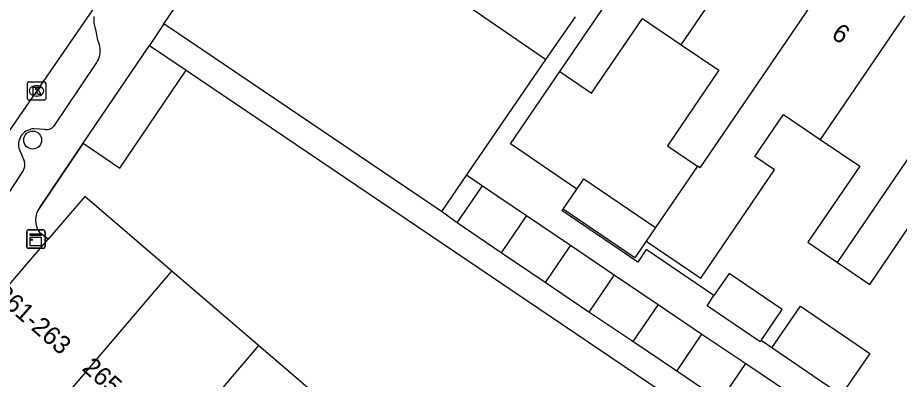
# Model space of a CAD drawing. Extents: x 159280 to 160375, y 384531 to 385872.
# Drawn here: x 159813.38 to 159861.5, y 384790.93 to 384810.68 of the extents above; entities that cross this region are included whole.
import ezdxf

# ---------------------------------------------------------------- set-up
doc = ezdxf.new("R2010")
doc.units = 0
for name, color, linetype in [('IMGEO_Boom', 7, 'Continuous'), ('IMGEO_Kast', 7, 'Continuous'), ('IMGEO_Kolk', 7, 'Continuous'), ('IMGEO_Muur', 7, 'Continuous'), ('IMGEO_Pand', 7, 'Continuous'), ('IMGEO_Pand_nummerreeks', 7, 'Continuous'), ('IMGEO_Rijbaan_lokaal_open', 7, 'Continuous'), ('IMGEO_Voetpad_open', 7, 'Continuous')]:
    doc.layers.add(name, color=color, linetype=linetype)

msp = doc.modelspace()

# ---------------------------------------------------------------- linework, layer by layer
at = {"layer": 'IMGEO_Boom'}
msp.add_circle((159814.205, 384803.995), 0.489, dxfattribs=at)
at = {"layer": 'IMGEO_Kast'}
for p, q in [((159813.878, 384798.159), (159813.878, 384799)), ((159813.878, 384799), (159813.878, 384798.159)), ((159813.953, 384799.084), (159814.794, 384799.084)), ((159814.794, 384799.084), (159813.953, 384799.084)), ((159814.878, 384799.009), (159814.878, 384798.168)), ((159814.878, 384798.168), (159814.878, 384799.009)), ((159814.803, 384798.084), (159813.962, 384798.084)), ((159813.962, 384798.084), (159814.803, 384798.084))]:
    msp.add_line(p, q, dxfattribs=at)
for points in [[(159814.073, 384798.874), (159814.673, 384798.874), (159814.673, 384798.789), (159814.073, 384798.789), (159814.073, 384798.874)], [(159814.073, 384798.699), (159814.673, 384798.699), (159814.673, 384798.21), (159814.073, 384798.21), (159814.073, 384798.699)]]:
    msp.add_lwpolyline(points, dxfattribs=at)
msp.add_circle((159814.157, 384798.548), 0.0377, dxfattribs=at)
for centre, start, end in [((159814.8, 384799.006), 2.4484, 94.2845), ((159814.8, 384799.006), 2.4484, 94.2845), ((159813.956, 384799.006), 92.4484, 184.2845), ((159813.956, 384799.006), 92.4484, 184.2845), ((159813.956, 384798.162), 182.4484, 274.2845), ((159813.956, 384798.162), 182.4484, 274.2845), ((159814.8, 384798.162), 272.4484, 4.2845), ((159814.8, 384798.162), 272.4484, 4.2845)]:
    msp.add_arc(centre, 0.0779, start, end, dxfattribs=at)
at = {"layer": 'IMGEO_Kolk'}
for p, q in [((159813.914, 384806.255), (159813.914, 384807.107)), ((159813.989, 384807.181), (159814.841, 384807.181)), ((159814.402, 384806.961), (159814.427, 384806.961)), ((159814.915, 384807.107), (159814.915, 384806.255)), ((159814.425, 384806.401), (159814.4, 384806.401)), ((159814.841, 384806.181), (159813.989, 384806.181))]:
    msp.add_line(p, q, dxfattribs=at)
for points in [[(159813.914, 384806.255), (159813.914, 384807.107)], [(159813.989, 384807.181), (159814.841, 384807.181)], [(159814.235, 384806.881), (159814.358, 384806.881), (159814.358, 384806.73), (159814.488, 384806.881), (159814.652, 384806.881), (159814.506, 384806.73), (159814.659, 384806.481), (159814.507, 384806.481), (159814.422, 384806.645), (159814.358, 384806.578), (159814.358, 384806.481), (159814.235, 384806.481), (159814.235, 384806.881)], [(159814.915, 384807.107), (159814.915, 384806.255)], [(159814.841, 384806.181), (159813.989, 384806.181)]]:
    msp.add_lwpolyline(points, dxfattribs=at)
for centre, start, end in [((159813.991, 384807.105), 91.552, 178.448), ((159813.991, 384807.105), 91.552, 178.448), ((159814.839, 384807.105), 1.552, 88.448), ((159814.839, 384807.105), 1.552, 88.448), ((159813.991, 384806.257), 181.552, 268.448), ((159813.991, 384806.257), 181.552, 268.448), ((159814.839, 384806.257), 271.552, 358.448), ((159814.839, 384806.257), 271.552, 358.448)]:
    msp.add_arc(centre, 0.0765, start, end, dxfattribs=at)
for centre, major_axis, ratio, start_param, end_param in [((159814.401, 384806.681), (-0.387, 0.002), 0.722429, 4.712389, 7.853982), ((159814.426, 384806.681), (-0.39, 0.002), 0.717154, 1.570796, 4.712389)]:
    msp.add_ellipse(centre, major_axis=major_axis, ratio=ratio, start_param=start_param, end_param=end_param, dxfattribs=at)
at = {"layer": 'IMGEO_Muur'}
for points in [[(159816.958, 384803.823), (159814.598, 384800.315)], [(159815.059, 384798.586), (159814.594, 384798.937)]]:
    msp.add_lwpolyline(points, dxfattribs=at)
msp.add_arc((159815.493, 384799.623), 1.131, 142.3162, 217.3511, dxfattribs=at)
at = {"layer": 'IMGEO_Pand'}
for points in [[(159821.369, 384810.341), (159827.097, 384818.804)], [(159842.964, 384807.74), (159847.547, 384814.471), (159850.361, 384818.603)], [(159849.598, 384809.194), (159854.217, 384815.978)], [(159857.686, 384812.866), (159850.613, 384802.479), (159850.476, 384802.572)], [(159842.197, 384808.391), (159837.892, 384811.347), (159837.962, 384811.45)], [(159843.804, 384810.731), (159842.197, 384808.391)], [(159842.964, 384807.74), (159844.706, 384806.554), (159847.484, 384810.634), (159849.598, 384809.194)], [(159861.787, 384810.787), (159857.182, 384804.026)], [(159836.505, 384800.099), (159825.511, 384807.539), (159821.369, 384810.341)], [(159849.598, 384809.194), (159851.639, 384807.804), (159848.837, 384803.688), (159850.476, 384802.572)], [(159816.958, 384803.823), (159820.573, 384809.165)], [(159820.573, 384809.165), (159822.578, 384807.809)], [(159842.197, 384808.391), (159837.88, 384802.102)], [(159816.958, 384803.823), (159818.963, 384802.467), (159822.578, 384807.809)], [(159858.125, 384797.31), (159865.24, 384807.756)], [(159847.689, 384798.478), (159850.657, 384796.457), (159854.682, 384802.367), (159853.605, 384803.1), (159855.169, 384805.397), (159857.182, 384804.026)], [(159857.182, 384804.026), (159859.335, 384802.561), (159856.509, 384798.41), (159858.125, 384797.31)], [(159850.476, 384802.572), (159848.194, 384799.221)], [(159837.88, 384802.102), (159836.505, 384800.099)], [(159837.373, 384799.466), (159838.751, 384801.504)], [(159838.751, 384801.504), (159841.152, 384799.88)], [(159843.905, 384801.317), (159844.288, 384801.88), (159848.194, 384799.221)], [(159843.161, 384800.225), (159843.905, 384801.317)], [(159821.793, 384796.841), (159817.054, 384800.909), (159815.059, 384798.586)], [(159847.689, 384798.478), (159847.067, 384797.566), (159843.161, 384800.225)], [(159858.125, 384797.31), (159859.882, 384796.114), (159862.724, 384800.289), (159864.738, 384798.918)], [(159841.152, 384799.88), (159839.773, 384797.843)], [(159841.152, 384799.88), (159843.545, 384798.261)], [(159839.773, 384797.843), (159837.373, 384799.466)], [(159848.194, 384799.221), (159847.689, 384798.478)], [(159810.546, 384793.33), (159815.059, 384798.586)], [(159843.545, 384798.261), (159842.167, 384796.223)], [(159843.545, 384798.261), (159845.939, 384796.641)], [(159842.167, 384796.223), (159839.773, 384797.843)], [(159815.322, 384789.229), (159821.793, 384796.841)], [(159826.532, 384792.771), (159821.793, 384796.841)], [(159853.948, 384793.045), (159855.104, 384794.742), (159852.209, 384796.714), (159851.382, 384795.5)], [(159844.561, 384794.604), (159842.167, 384796.223)], [(159845.939, 384796.641), (159844.561, 384794.604)], [(159845.939, 384796.641), (159848.333, 384795.022)], [(159853.948, 384793.045), (159853.902, 384792.977), (159851.006, 384794.948), (159851.382, 384795.5)], [(159848.333, 384795.022), (159846.955, 384792.985)], [(159848.333, 384795.022), (159850.727, 384793.403)], [(159854.541, 384792.641), (159856.097, 384794.927), (159859.885, 384792.347), (159858.8, 384790.754)], [(159846.955, 384792.985), (159844.561, 384794.604)], [(159849.349, 384791.366), (159850.727, 384793.403)], [(159850.727, 384793.403), (159853.12, 384791.784)], [(159849.349, 384791.366), (159846.955, 384792.985)], [(159826.532, 384792.771), (159820.075, 384785.174)], [(159831.272, 384788.701), (159826.532, 384792.771)], [(159858.8, 384790.754), (159858.329, 384790.062), (159854.541, 384792.641)], [(159851.742, 384789.746), (159853.12, 384791.784)], [(159853.12, 384791.784), (159855.514, 384790.164)], [(159851.742, 384789.746), (159849.349, 384791.366)]]:
    msp.add_lwpolyline(points, dxfattribs=at)
at = {"layer": 'IMGEO_Rijbaan_lokaal_open'}
msp.add_lwpolyline([(159817.762, 384811.531), (159808.223, 384797.717)], dxfattribs=at)
at = {"layer": 'IMGEO_Voetpad_open'}
for points in [[(159817.536, 384810.737), (159817.534, 384810.571), (159817.547, 384810.405), (159817.576, 384810.241), (159817.618, 384810.081), (159817.632, 384810.038), (159817.741, 384809.455), (159817.754, 384809.428), (159817.798, 384809.324), (159817.832, 384809.216), (159817.857, 384809.106), (159817.871, 384808.994), (159817.876, 384808.881), (159817.87, 384808.768), (159817.855, 384808.656), (159817.829, 384808.546), (159817.794, 384808.438), (159817.749, 384808.334), (159817.695, 384808.235), (159815.343, 384804.734)], [(159821.369, 384810.341), (159820.573, 384809.165)], [(159822.578, 384807.809), (159896.975, 384757.494), (159896.887, 384757.365), (159889.352, 384746.225), (159885.124, 384744.266), (159883.411, 384743.933)], [(159843.905, 384801.317), (159840.272, 384803.786), (159842.964, 384807.74)], [(159814.873, 384804.572), (159814.292, 384804.608)], [(159813.444, 384803.561), (159813.76, 384802.8)], [(159814.598, 384800.315), (159816.958, 384803.823)], [(159813.687, 384802.324), (159811.635, 384799.196), (159811.6, 384799.153), (159811.49, 384799.032), (159811.37, 384798.922), (159811.24, 384798.823), (159811.102, 384798.736), (159810.956, 384798.662), (159810.805, 384798.6), (159810.649, 384798.553), (159810.489, 384798.52), (159809.829, 384798.472), (159809.563, 384798.422), (159809.302, 384798.347), (159809.048, 384798.25), (159808.805, 384798.131), (159808.573, 384797.99), (159808.355, 384797.83), (159808.223, 384797.717)], [(159837.88, 384802.102), (159838.751, 384801.504)], [(159837.373, 384799.466), (159836.505, 384800.099)], [(159851.382, 384795.5), (159847.689, 384798.01), (159847.224, 384797.326), (159843.084, 384800.141), (159843.161, 384800.225)], [(159815.059, 384798.586), (159814.594, 384798.937)], [(159854.541, 384792.641), (159853.948, 384793.045)]]:
    msp.add_lwpolyline(points, dxfattribs=at)
for centre, radius, start, end in [((159814.298, 384803.736), 0.872, 90.4001, 191.5896), ((159814.97, 384805.053), 0.49, 258.5665, 319.4697), ((159813.239, 384802.636), 0.546, 325.124, 17.4379), ((159815.493, 384799.623), 1.131, 142.3162, 217.3511)]:
    msp.add_arc(centre, radius, start, end, dxfattribs=at)

# ---------------------------------------------------------------- texts
at = {"layer": 'IMGEO_Pand_nummerreeks'}
for s, rotation, p in [('6', 325.7429, (159857.728, 384809.617)), ('261-263', 318.8158, (159812.056, 384795.445)), ('265-267', 318.3689, (159816.844, 384791.471))]:
    msp.add_text(s, height=1, rotation=rotation, dxfattribs=at).set_placement(p)

doc.saveas('drawing.dxf')
